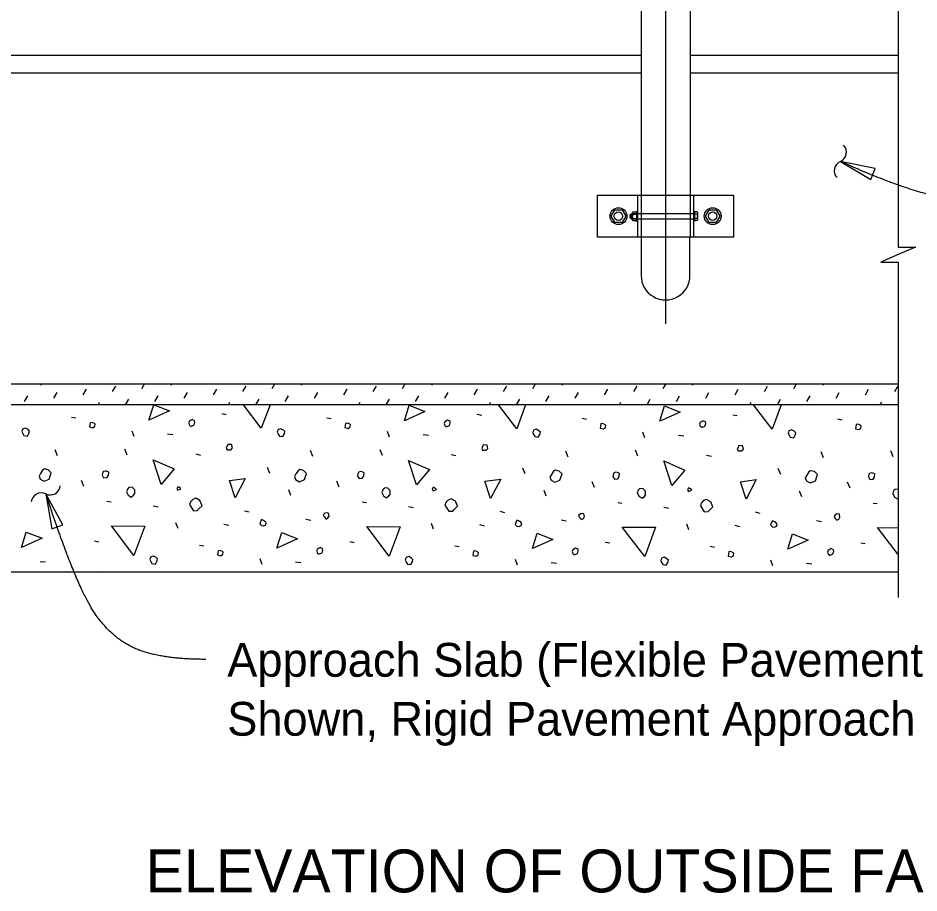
# Model space of a CAD drawing. Extents: x 0 to 41, y -96 to 25.
# Drawn here: x 11.46 to 16.84, y 9.6 to 14.82 of the extents above; entities that cross this region are included whole.
import ezdxf

# ---------------------------------------------------------------- set-up
doc = ezdxf.new("R2010")
doc.units = 0
for name, color, linetype in [('CL_Major', 7, 'Continuous'), ('Dimension', 7, 'Continuous'), ('Miscellaneous', 7, 'Continuous'), ('SteelMisc', 7, 'Continuous'), ('SteelMisc_h', 7, 'Continuous'), ('SupstrConc', 7, 'Continuous')]:
    doc.layers.add(name, color=color, linetype=linetype)

msp = doc.modelspace()

# ---------------------------------------------------------------- linework, layer by layer
at = {"layer": 'CL_Major'}
msp.add_line((15.3237, 24.2317), (15.3237, 12.9956), dxfattribs=at)
at = {"layer": 'Dimension'}
msp.add_lwpolyline([(16.7107, 15.3052), (16.7107, 13.4544), (16.814, 13.4544), (16.7107, 13.4094), (16.6074, 13.3644), (16.7107, 13.3644), (16.7107, 11.3636)], dxfattribs=at)
for points in [[(16.367, 13.9658), (16.5479, 13.8568), (16.5737, 13.9225)], [(11.6266, 11.9812), (11.6612, 11.7729), (11.7279, 11.7959)]]:
    msp.add_lwpolyline(points, close=True, dxfattribs=at)
for centre, start, end in [((16.3438, 14.0201), 292.7091, 44.4364), ((16.3898, 13.9101), 112.7091, 224.4364), ((11.599, 11.9277), 63.2317, 174.9589), ((11.6527, 12.0341), 243.2317, 354.9589)]:
    msp.add_arc(centre, 0.0596, start, end, dxfattribs=at)
for points in [[(17.694, 13.7089), (17.6241, 13.7089), (16.9246, 13.7089), (16.367, 13.9658)], [(12.5802, 10.9934), (12.3148, 10.9934), (12.0163, 11.1179), (11.8007, 11.4499), (11.6266, 11.9812)]]:
    msp.add_open_spline(points, degree=2, dxfattribs=at)
at = {"layer": 'Miscellaneous'}
for p, q in [((15.1162, 13.6316), (15.1162, 13.6437)), ((15.1219, 13.6316), (15.1219, 13.6437)), ((11.5963, 12.6302), (11.6011, 12.6385)), ((12.1991, 12.6107), (12.2152, 12.6385)), ((12.3741, 12.6302), (12.379, 12.6385)), ((12.977, 12.6107), (12.993, 12.6385)), ((13.152, 12.6302), (13.1568, 12.6385)), ((13.7548, 12.6107), (13.7708, 12.6385)), ((13.9298, 12.6302), (13.9346, 12.6385)), ((14.5326, 12.6107), (14.5487, 12.6385)), ((14.7076, 12.6302), (14.7124, 12.6385)), ((15.3104, 12.6107), (15.3265, 12.6385)), ((15.4854, 12.6302), (15.4902, 12.6385)), ((16.0882, 12.6107), (16.1043, 12.6385)), ((16.2632, 12.6302), (16.268, 12.6385)), ((11.6741, 12.5524), (11.6936, 12.586)), ((11.8491, 12.5718), (11.8686, 12.6054)), ((12.0241, 12.5913), (12.0436, 12.6249)), ((12.4519, 12.5524), (12.4714, 12.586)), ((12.6269, 12.5718), (12.6464, 12.6054)), ((12.8019, 12.5913), (12.8214, 12.6249)), ((13.2297, 12.5524), (13.2492, 12.586)), ((13.4048, 12.5718), (13.4242, 12.6054)), ((13.5798, 12.5913), (13.5992, 12.6249)), ((14.0076, 12.5524), (14.027, 12.586)), ((14.1826, 12.5718), (14.202, 12.6054)), ((14.3576, 12.5913), (14.377, 12.6249)), ((14.7854, 12.5524), (14.8048, 12.586)), ((14.9604, 12.5718), (14.9798, 12.6054)), ((15.1354, 12.5913), (15.1548, 12.6249)), ((15.5632, 12.5524), (15.5826, 12.586)), ((15.7382, 12.5718), (15.7577, 12.6054)), ((15.9132, 12.5913), (15.9327, 12.6249)), ((16.341, 12.5524), (16.3605, 12.586)), ((16.516, 12.5718), (16.5355, 12.6054)), ((16.691, 12.5913), (16.7105, 12.6249)), ((11.4991, 12.533), (11.5185, 12.5665)), ((11.9382, 12.5135), (11.9463, 12.5276)), ((12.1019, 12.5135), (12.1214, 12.5471)), ((12.2769, 12.533), (12.2964, 12.5665)), ((12.716, 12.5135), (12.7242, 12.5276)), ((12.8797, 12.5135), (12.8992, 12.5471)), ((13.0547, 12.533), (13.0742, 12.5665)), ((13.4938, 12.5135), (13.502, 12.5276)), ((13.6575, 12.5135), (13.677, 12.5471)), ((13.8326, 12.533), (13.852, 12.5665)), ((14.2716, 12.5135), (14.2798, 12.5276)), ((14.4354, 12.5135), (14.4548, 12.5471)), ((14.6104, 12.533), (14.6298, 12.5665)), ((15.0494, 12.5135), (15.0576, 12.5276)), ((15.2132, 12.5135), (15.2326, 12.5471)), ((15.3882, 12.533), (15.4076, 12.5665)), ((15.8272, 12.5135), (15.8354, 12.5276)), ((15.991, 12.5135), (16.0104, 12.5471)), ((16.166, 12.533), (16.1855, 12.5665)), ((16.6051, 12.5135), (16.6133, 12.5276)), ((11.7786, 12.4393), (11.8051, 12.434)), ((12.6766, 12.4605), (12.7031, 12.4552)), ((13.3024, 12.4357), (13.3289, 12.4304)), ((14.2004, 12.4569), (14.227, 12.4516)), ((14.8262, 12.4322), (14.8527, 12.4269)), ((15.7243, 12.4534), (15.7508, 12.4481)), ((16.35, 12.4287), (16.3766, 12.4234)), ((12.1534, 12.3226), (12.141, 12.3562)), ((12.3531, 12.3385), (12.3849, 12.335)), ((13.6772, 12.3191), (13.6648, 12.3526)), ((13.8769, 12.335), (13.9088, 12.3314)), ((15.201, 12.3155), (15.1886, 12.3491)), ((15.4008, 12.3314), (15.4326, 12.3279)), ((11.6955, 12.2077), (11.6814, 12.243)), ((12.1109, 12.213), (12.0968, 12.2483)), ((12.5211, 12.2201), (12.5493, 12.213)), ((13.2193, 12.2041), (13.2052, 12.2395)), ((13.6348, 12.2095), (13.6206, 12.2448)), ((14.0449, 12.2165), (14.0732, 12.2095)), ((14.7431, 12.2006), (14.729, 12.236)), ((15.1586, 12.2059), (15.1444, 12.2413)), ((15.5687, 12.213), (15.597, 12.2059)), ((16.267, 12.1971), (16.2528, 12.2324)), ((16.6824, 12.2024), (16.6682, 12.2377)), ((12.963, 12.1034), (12.9489, 12.1387)), ((14.4868, 12.0998), (14.4727, 12.1352)), ((16.0106, 12.0963), (15.9965, 12.1317)), ((11.8528, 12.0256), (11.8387, 12.061)), ((13.3767, 12.0221), (13.3625, 12.0574)), ((14.9005, 12.0185), (14.8863, 12.0539)), ((16.4243, 12.015), (16.4102, 12.0504)), ((13.0885, 11.9708), (13.0761, 12.0044)), ((14.6123, 11.9673), (14.6, 12.0009)), ((16.1361, 11.9637), (16.1238, 11.9973)), ((11.9907, 11.9372), (12.0155, 11.9337)), ((13.5145, 11.9337), (13.5393, 11.9301)), ((12.2665, 11.9089), (12.2966, 11.9036)), ((12.811, 11.8806), (12.8393, 11.8736)), ((13.7903, 11.9054), (13.8204, 11.9001)), ((15.0384, 11.9301), (15.0631, 11.9266)), ((15.3141, 11.9019), (15.3442, 11.8966)), ((16.5622, 11.9266), (16.5869, 11.9231)), ((13.1769, 11.8294), (13.207, 11.8241)), ((14.3348, 11.8771), (14.3631, 11.87)), ((14.7007, 11.8258), (14.7308, 11.8205)), ((15.8586, 11.8736), (15.8869, 11.8665)), ((12.415, 11.7746), (12.4026, 11.8082)), ((12.689, 11.8011), (12.7173, 11.794)), ((13.9388, 11.771), (13.9264, 11.8046)), ((14.2128, 11.7976), (14.2411, 11.7905)), ((15.4626, 11.7675), (15.4503, 11.8011)), ((15.7366, 11.794), (15.7649, 11.787)), ((16.2245, 11.8223), (16.2546, 11.817)), ((11.9165, 11.7003), (11.943, 11.695)), ((12.5423, 11.6756), (12.5688, 11.6703)), ((13.4403, 11.6968), (13.4668, 11.6915)), ((14.0661, 11.672), (14.0926, 11.6667)), ((14.9641, 11.6933), (14.9906, 11.688)), ((15.5899, 11.6685), (15.6164, 11.6632)), ((16.4879, 11.6897), (16.5144, 11.6844)), ((11.593, 11.5784), (11.6248, 11.5748)), ((12.917, 11.5589), (12.9047, 11.5925)), ((13.1168, 11.5748), (13.1486, 11.5713)), ((14.4409, 11.5554), (14.4285, 11.589)), ((14.6406, 11.5713), (14.6724, 11.5678)), ((15.9647, 11.5518), (15.9523, 11.5854)), ((16.1644, 11.5678), (16.1963, 11.5642))]:
    msp.add_line(p, q, dxfattribs=at)
for points in [[(12.2418, 12.4216), (12.27, 12.5135), (12.3637, 12.4764), (12.2418, 12.4216)], [(12.9117, 12.3739), (12.8056, 12.5135)], [(12.9639, 12.5135), (12.9117, 12.3739)], [(13.7656, 12.418), (13.7939, 12.51), (13.8875, 12.4728), (13.7656, 12.418)], [(14.4356, 12.3703), (14.3267, 12.5135)], [(14.4891, 12.5135), (14.4356, 12.3703)], [(15.2894, 12.4145), (15.3177, 12.5064), (15.4114, 12.4693), (15.2894, 12.4145)], [(15.9594, 12.3668), (15.8479, 12.5135)], [(16.0142, 12.5135), (15.9594, 12.3668)], [(12.4892, 12.3862), (12.4963, 12.3862), (12.5105, 12.3933), (12.5158, 12.4092), (12.514, 12.418), (12.4999, 12.4251), (12.4822, 12.4145), (12.4786, 12.4039), (12.4822, 12.3933), (12.4892, 12.3862)], [(14.0131, 12.3827), (14.0201, 12.3827), (14.0343, 12.3898), (14.0396, 12.4057), (14.0378, 12.4145), (14.0237, 12.4216), (14.006, 12.411), (14.0025, 12.4004), (14.006, 12.3898), (14.0131, 12.3827)], [(15.5369, 12.3792), (15.5439, 12.3792), (15.5581, 12.3862), (15.5634, 12.4021), (15.5616, 12.411), (15.5475, 12.418), (15.5298, 12.4074), (15.5263, 12.3968), (15.5298, 12.3862), (15.5369, 12.3792)], [(11.4869, 12.3456), (11.4958, 12.3297), (11.517, 12.3261), (11.5258, 12.342), (11.5293, 12.3562), (11.5205, 12.365), (11.5046, 12.3739), (11.4887, 12.3686), (11.4834, 12.3526), (11.4869, 12.3456)], [(11.8864, 12.3809), (11.9059, 12.3756), (11.9183, 12.3845), (11.92, 12.3968), (11.9165, 12.4004), (11.9023, 12.4074), (11.89, 12.4057), (11.8882, 12.3933), (11.8864, 12.3809)], [(13.0107, 12.342), (13.0196, 12.3261), (13.0408, 12.3226), (13.0496, 12.3385), (13.0532, 12.3526), (13.0443, 12.3615), (13.0284, 12.3703), (13.0125, 12.365), (13.0072, 12.3491), (13.0107, 12.342)], [(13.4103, 12.3774), (13.4297, 12.3721), (13.4421, 12.3809), (13.4438, 12.3933), (13.4403, 12.3968), (13.4262, 12.4039), (13.4138, 12.4021), (13.412, 12.3898), (13.4103, 12.3774)], [(14.5346, 12.3385), (14.5434, 12.3226), (14.5646, 12.3191), (14.5734, 12.335), (14.577, 12.3491), (14.5681, 12.3579), (14.5522, 12.3668), (14.5363, 12.3615), (14.531, 12.3456), (14.5346, 12.3385)], [(14.9341, 12.3739), (14.9535, 12.3686), (14.9659, 12.3774), (14.9677, 12.3898), (14.9641, 12.3933), (14.95, 12.4004), (14.9376, 12.3986), (14.9358, 12.3862), (14.9341, 12.3739)], [(16.0584, 12.335), (16.0672, 12.3191), (16.0884, 12.3155), (16.0973, 12.3314), (16.1008, 12.3456), (16.092, 12.3544), (16.076, 12.3632), (16.0601, 12.3579), (16.0548, 12.342), (16.0584, 12.335)], [(16.4579, 12.3703), (16.4773, 12.365), (16.4897, 12.3739), (16.4915, 12.3862), (16.4879, 12.3898), (16.4738, 12.3968), (16.4614, 12.3951), (16.4596, 12.3827), (16.4579, 12.3703)], [(12.7084, 12.2448), (12.7297, 12.2448), (12.7403, 12.2554), (12.735, 12.2749), (12.712, 12.2766), (12.7084, 12.266), (12.7031, 12.2572), (12.7084, 12.2448), (12.7049, 12.2483)], [(14.2323, 12.2413), (14.2535, 12.2413), (14.2641, 12.2519), (14.2588, 12.2713), (14.2358, 12.2731), (14.2323, 12.2625), (14.227, 12.2536), (14.2323, 12.2413), (14.2287, 12.2448)], [(15.7561, 12.2377), (15.7773, 12.2377), (15.7879, 12.2483), (15.7826, 12.2678), (15.7596, 12.2696), (15.7561, 12.2589), (15.7508, 12.2501), (15.7561, 12.2377), (15.7525, 12.2413)], [(12.3142, 12.038), (12.2665, 12.1847), (12.392, 12.1299), (12.3142, 12.038)], [(13.838, 12.0344), (13.7903, 12.1812), (13.9158, 12.1264), (13.838, 12.0344)], [(15.3619, 12.0309), (15.3141, 12.1776), (15.4396, 12.1228), (15.3619, 12.0309)], [(11.593, 12.0698), (11.616, 12.0574), (11.646, 12.0698), (11.6584, 12.1069), (11.6407, 12.1246), (11.6177, 12.1299), (11.6071, 12.1228), (11.5948, 12.1034), (11.5859, 12.0875), (11.593, 12.0698)], [(11.9624, 12.0928), (11.9713, 12.0769), (11.9907, 12.0786), (11.9996, 12.091), (12.0013, 12.1105), (11.989, 12.1158), (11.9801, 12.1175), (11.9695, 12.114), (11.966, 12.1105), (11.9624, 12.0928)], [(13.1168, 12.0663), (13.1398, 12.0539), (13.1698, 12.0663), (13.1822, 12.1034), (13.1645, 12.1211), (13.1415, 12.1264), (13.1309, 12.1193), (13.1186, 12.0998), (13.1097, 12.0839), (13.1168, 12.0663)], [(13.4863, 12.0892), (13.4951, 12.0733), (13.5145, 12.0751), (13.5234, 12.0875), (13.5252, 12.1069), (13.5128, 12.1122), (13.5039, 12.114), (13.4933, 12.1105), (13.4898, 12.1069), (13.4863, 12.0892)], [(14.6406, 12.0627), (14.6636, 12.0504), (14.6936, 12.0627), (14.706, 12.0998), (14.6883, 12.1175), (14.6654, 12.1228), (14.6548, 12.1158), (14.6424, 12.0963), (14.6335, 12.0804), (14.6406, 12.0627)], [(15.0101, 12.0857), (15.0189, 12.0698), (15.0384, 12.0716), (15.0472, 12.0839), (15.049, 12.1034), (15.0366, 12.1087), (15.0278, 12.1105), (15.0172, 12.1069), (15.0136, 12.1034), (15.0101, 12.0857)], [(16.1644, 12.0592), (16.1874, 12.0468), (16.2175, 12.0592), (16.2298, 12.0963), (16.2122, 12.114), (16.1892, 12.1193), (16.1786, 12.1122), (16.1662, 12.0928), (16.1574, 12.0769), (16.1644, 12.0592)], [(16.5339, 12.0822), (16.5427, 12.0663), (16.5622, 12.068), (16.571, 12.0804), (16.5728, 12.0998), (16.5604, 12.1052), (16.5516, 12.1069), (16.541, 12.1034), (16.5374, 12.0998), (16.5339, 12.0822)], [(12.7562, 11.9567), (12.7226, 12.061), (12.8163, 12.0733), (12.7562, 11.9567)], [(14.28, 11.9531), (14.2464, 12.0574), (14.3401, 12.0698), (14.28, 11.9531)], [(15.8038, 11.9496), (15.7702, 12.0539), (15.8639, 12.0663), (15.8038, 11.9496)], [(12.1074, 11.9938), (12.118, 11.9726), (12.1357, 11.962), (12.1498, 11.9726), (12.1569, 11.9832), (12.1569, 12.0044), (12.141, 12.0203), (12.1215, 12.0185), (12.1127, 12.0097), (12.1074, 11.9938)], [(12.4132, 12.0026), (12.4327, 12.0115), (12.4256, 12.0185), (12.4132, 12.0238), (12.4079, 12.0115), (12.4132, 12.0026)], [(13.6312, 11.9902), (13.6418, 11.969), (13.6595, 11.9584), (13.6736, 11.969), (13.6807, 11.9796), (13.6807, 12.0009), (13.6648, 12.0168), (13.6454, 12.015), (13.6365, 12.0062), (13.6312, 11.9902)], [(13.937, 11.9991), (13.9565, 12.0079), (13.9494, 12.015), (13.937, 12.0203), (13.9317, 12.0079), (13.937, 11.9991)], [(15.155, 11.9867), (15.1656, 11.9655), (15.1833, 11.9549), (15.1975, 11.9655), (15.2045, 11.9761), (15.2045, 11.9973), (15.1886, 12.0132), (15.1692, 12.0115), (15.1603, 12.0026), (15.155, 11.9867)], [(15.4609, 11.9956), (15.4803, 12.0044), (15.4732, 12.0115), (15.4609, 12.0168), (15.4556, 12.0044), (15.4609, 11.9956)], [(16.7107, 12.0095), (16.693, 12.0079), (16.6842, 11.9991), (16.6789, 11.9832)], [(12.4839, 11.9178), (12.5069, 11.8806), (12.5299, 11.8824), (12.5387, 11.8913), (12.5582, 11.9107), (12.5458, 11.9408), (12.5211, 11.9549), (12.5034, 11.9478), (12.4892, 11.9337), (12.4839, 11.9178)], [(14.0078, 11.9142), (14.0307, 11.8771), (14.0537, 11.8789), (14.0626, 11.8877), (14.082, 11.9072), (14.0696, 11.9372), (14.0449, 11.9514), (14.0272, 11.9443), (14.0131, 11.9301), (14.0078, 11.9142)], [(15.5316, 11.9107), (15.5546, 11.8736), (15.5775, 11.8753), (15.5864, 11.8842), (15.6058, 11.9036), (15.5934, 11.9337), (15.5687, 11.9478), (15.551, 11.9408), (15.5369, 11.9266), (15.5316, 11.9107)], [(16.6789, 11.9832), (16.6895, 11.962), (16.7071, 11.9514), (16.7107, 11.954)], [(12.9135, 11.7923), (12.9259, 11.7905), (12.9383, 11.7958), (12.9418, 11.8064), (12.9365, 11.8152), (12.9259, 11.8223), (12.9135, 11.8276), (12.9064, 11.8135), (12.9029, 11.8029), (12.9135, 11.7923)], [(13.2883, 11.8418), (13.2989, 11.8311), (13.3095, 11.8382), (13.3166, 11.8488), (13.313, 11.8665), (13.3042, 11.8683), (13.2918, 11.8665), (13.2812, 11.8559), (13.2883, 11.8418)], [(14.8121, 11.8382), (14.8227, 11.8276), (14.8333, 11.8347), (14.8404, 11.8453), (14.8368, 11.863), (14.828, 11.8647), (14.8156, 11.863), (14.805, 11.8524), (14.8121, 11.8382)], [(16.3359, 11.8347), (16.3465, 11.8241), (16.3571, 11.8311), (16.3642, 11.8418), (16.3607, 11.8594), (16.3518, 11.8612), (16.3394, 11.8594), (16.3288, 11.8488), (16.3359, 11.8347)], [(12.1516, 11.6137), (12.0172, 11.7905), (12.217, 11.7887), (12.1516, 11.6137)], [(13.6754, 11.6102), (13.5411, 11.787), (13.7408, 11.7852), (13.6754, 11.6102)], [(14.4373, 11.7887), (14.4497, 11.787), (14.4621, 11.7923), (14.4656, 11.8029), (14.4603, 11.8117), (14.4497, 11.8188), (14.4373, 11.8241), (14.4303, 11.8099), (14.4267, 11.7993), (14.4373, 11.7887)], [(15.1992, 11.6066), (15.0649, 11.7834), (15.2646, 11.7817), (15.1992, 11.6066)], [(15.9611, 11.7852), (15.9735, 11.7834), (15.9859, 11.7887), (15.9894, 11.7993), (15.9841, 11.8082), (15.9735, 11.8152), (15.9611, 11.8205), (15.9541, 11.8064), (15.9505, 11.7958), (15.9611, 11.7852)], [(16.7107, 11.6194), (16.5887, 11.7799), (16.7107, 11.7788)], [(11.4816, 11.6614), (11.5099, 11.7534), (11.6036, 11.7162), (11.4816, 11.6614)], [(13.0054, 11.6579), (13.0337, 11.7498), (13.1274, 11.7127), (13.0054, 11.6579)], [(14.5292, 11.6544), (14.5575, 11.7463), (14.6512, 11.7092), (14.5292, 11.6544)], [(16.0531, 11.6508), (16.0813, 11.7428), (16.175, 11.7056), (16.0531, 11.6508)], [(12.6501, 11.6172), (12.6696, 11.6119), (12.6819, 11.6208), (12.6837, 11.6332), (12.6802, 11.6367), (12.666, 11.6438), (12.6536, 11.642), (12.6519, 11.6296), (12.6501, 11.6172)], [(13.2529, 11.6226), (13.26, 11.6226), (13.2741, 11.6296), (13.2794, 11.6455), (13.2777, 11.6544), (13.2635, 11.6614), (13.2458, 11.6508), (13.2423, 11.6402), (13.2458, 11.6296), (13.2529, 11.6226)], [(14.1739, 11.6137), (14.1934, 11.6084), (14.2057, 11.6172), (14.2075, 11.6296), (14.204, 11.6332), (14.1898, 11.6402), (14.1775, 11.6385), (14.1757, 11.6261), (14.1739, 11.6137)], [(14.7767, 11.619), (14.7838, 11.619), (14.7979, 11.6261), (14.8033, 11.642), (14.8015, 11.6508), (14.7873, 11.6579), (14.7697, 11.6473), (14.7661, 11.6367), (14.7697, 11.6261), (14.7767, 11.619)], [(15.6977, 11.6102), (15.7172, 11.6049), (15.7296, 11.6137), (15.7313, 11.6261), (15.7278, 11.6296), (15.7137, 11.6367), (15.7013, 11.6349), (15.6995, 11.6226), (15.6977, 11.6102)], [(16.3005, 11.6155), (16.3076, 11.6155), (16.3218, 11.6226), (16.3271, 11.6385), (16.3253, 11.6473), (16.3112, 11.6544), (16.2935, 11.6438), (16.2899, 11.6332), (16.2935, 11.6226), (16.3005, 11.6155)], [(12.2506, 11.5819), (12.2594, 11.566), (12.2806, 11.5624), (12.2895, 11.5784), (12.293, 11.5925), (12.2842, 11.6013), (12.2683, 11.6102), (12.2524, 11.6049), (12.2471, 11.589), (12.2506, 11.5819)], [(13.7744, 11.5784), (13.7832, 11.5624), (13.8045, 11.5589), (13.8133, 11.5748), (13.8168, 11.589), (13.808, 11.5978), (13.7921, 11.6066), (13.7762, 11.6013), (13.7709, 11.5854), (13.7744, 11.5784)], [(15.2982, 11.5748), (15.3071, 11.5589), (15.3283, 11.5554), (15.3371, 11.5713), (15.3407, 11.5854), (15.3318, 11.5943), (15.3159, 11.6031), (15.3, 11.5978), (15.2947, 11.5819), (15.2982, 11.5748)], [(11.9752, 11.5135), (11.9748, 11.5147), (11.9518, 11.5165), (11.9508, 11.5135)]]:
    msp.add_lwpolyline(points, dxfattribs=at)
at = {"layer": 'SteelMisc'}
for p, q in [((15.1779, 15.0135), (15.1779, 13.7635)), ((15.4696, 15.0135), (15.4696, 13.7635)), ((14.9178, 13.7635), (15.7297, 13.7635)), ((14.9178, 13.5135), (14.9178, 13.7635)), ((15.1571, 13.7635), (15.1571, 13.5135)), ((15.4904, 13.7635), (15.4904, 13.5135)), ((15.7297, 13.7635), (15.7297, 13.5135)), ((15.1255, 13.6564), (15.1255, 13.6207)), ((15.1304, 13.6646), (15.1505, 13.6646)), ((15.1505, 13.6688), (15.1505, 13.6082)), ((15.1505, 13.6688), (15.1571, 13.6688)), ((15.1505, 13.6646), (15.1505, 13.6126)), ((15.4967, 13.6688), (15.4906, 13.6688)), ((15.4967, 13.6688), (15.4967, 13.6082)), ((15.5114, 13.6645), (15.4967, 13.6645)), ((15.5165, 13.6191), (15.5165, 13.658)), ((15.1134, 13.6465), (15.119, 13.6531)), ((15.1134, 13.6288), (15.1134, 13.6465)), ((15.1134, 13.6288), (15.119, 13.6232)), ((15.119, 13.6531), (15.1255, 13.6531)), ((15.119, 13.6232), (15.119, 13.6531)), ((15.119, 13.6232), (15.1255, 13.6232)), ((15.1302, 13.6515), (15.1505, 13.6515)), ((15.1302, 13.6256), (15.1505, 13.6256)), ((15.1305, 13.6126), (15.1505, 13.6126)), ((15.1505, 13.6082), (15.1571, 13.6082)), ((15.4967, 13.6082), (15.4906, 13.6082)), ((15.5115, 13.6515), (15.4967, 13.6515)), ((15.5115, 13.6255), (15.4967, 13.6255)), ((15.5114, 13.6125), (15.4967, 13.6125)), ((15.7297, 13.5135), (14.9178, 13.5135)), ((15.1778, 13.5135), (15.1778, 13.2844)), ((15.4695, 13.2844), (15.4695, 13.5135))]:
    msp.add_line(p, q, dxfattribs=at)
for points in [[(15.0211, 13.6761), (15.0644, 13.6761), (15.0861, 13.6385), (15.0644, 13.601), (15.0211, 13.601), (14.9994, 13.6385)], [(15.5831, 13.6761), (15.6264, 13.6761), (15.6481, 13.6385), (15.6264, 13.601), (15.5831, 13.601), (15.5614, 13.6385)]]:
    msp.add_lwpolyline(points, close=True, dxfattribs=at)
for centre, radius in [((15.0428, 13.6385), 0.05), ((15.0428, 13.6385), 0.025), ((15.6047, 13.6385), 0.05), ((15.6047, 13.6385), 0.025)]:
    msp.add_circle(centre, radius, dxfattribs=at)
for centre, radius, start, end in [((15.1321, 13.658), 0.00674, 104.4891, 254.1889), ((15.5097, 13.658), 0.00673, 285.7823, 75.5404), ((15.145, 13.6385), 0.0196, 138.628, 221.372), ((15.1321, 13.6191), 0.00673, 105.7823, 255.5404), ((15.5097, 13.6191), 0.00674, 284.4891, 74.1889), ((15.4968, 13.6385), 0.0196, 318.628, 41.372)]:
    msp.add_arc(centre, radius, start, end, dxfattribs=at)
msp.add_ellipse((15.3237, 13.2844), major_axis=(0, 0.1458), ratio=0.999499, start_param=1.570796, end_param=4.712389, dxfattribs=at)
at = {"layer": 'SteelMisc_h'}
for p, q in [((15.1779, 13.7635), (15.1779, 13.5135)), ((15.4696, 13.7635), (15.4696, 13.5135)), ((15.4904, 13.6531), (15.1255, 13.6531)), ((15.1255, 13.6232), (15.4904, 13.6232))]:
    msp.add_line(p, q, dxfattribs=at)
at = {"layer": 'SupstrConc'}
for p, q in [((5.4696, 14.5986), (15.1779, 14.5986)), ((15.4696, 14.5986), (16.7107, 14.5986)), ((5.4696, 14.4945), (15.1779, 14.4945)), ((15.4696, 14.4945), (16.7107, 14.4945)), ((4.3237, 12.6385), (16.7107, 12.6385)), ((16.7107, 12.5135), (4.3237, 12.5135)), ((16.7107, 11.5135), (4.3237, 11.5135))]:
    msp.add_line(p, q, dxfattribs=at)

# ---------------------------------------------------------------- texts
at = {"layer": 'Dimension'}
for s, height, p in [('Approach Slab (Flexible Pavement Approach Slab ', 0.2016, (12.7086, 10.8899)), ('Shown, Rigid Pavement Approach Slab Similar)', 0.2016, (12.7086, 10.5379)), ('ELEVATION OF OUTSIDE FACE OF RAILING', 0.256001, (12.2221, 9.6027))]:
    msp.add_text(s, height=height, dxfattribs=at).set_placement(p)

doc.saveas('drawing.dxf')
